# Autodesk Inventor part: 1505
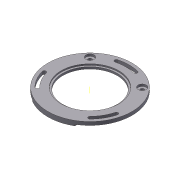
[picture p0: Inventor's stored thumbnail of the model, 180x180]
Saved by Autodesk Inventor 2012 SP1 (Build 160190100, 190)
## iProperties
Created: 2012-02
Part Number: 1505
Material: Aluminum-6061
Document SubType Name: Modeling
Designer: LACO
Density: 2.71 g/cm^3
Mass: 182.135 g
Surface Area: 295.447 cm^2
Volume: 67.2084 cm^3
Author: LACO
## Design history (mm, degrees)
sketch "Sketch1"
  geometry: C1 r 78.74 at (0, 0); A1 r 50.8 centre (0, 0) between (-41.102, 29.854) and (-41.102, -29.854); 3 further points
  constraints: 4 point on circle, 2 centre point, 2 coincident
  dimensions: "d25" = 157.48 diameter of C1; "d26" = 101.6 diameter of A1
extrude "Extrusion1" new body sketch "Sketch1" stored distance "d1" = 6.35; taper "d2" = 0 deg
sketch "Sketch5"
  geometry: C1 r 50.8 at (0, 0) reference; C2 r 78.74 at (0, 0) reference; C3 r 53.975 at (0, 0)
  constraints: 1 centre point, 1 coincident
  dimensions: "d36" = 3.175 radial gap between concentric circles of C1 C3
extrude "Extrusion3" cut sketch "Sketch5" distance "d37" = 2.54; taper "d38" = 0 deg
sketch "Sketch6"
  geometry: L1 (0, 0)-(78.74, 0); L2 (0, 0)-(76.057, -20.379); L3 (68.191, -39.37)-(0, 0); L4 (0, 0)-(55.678, -55.678); L5 (0, 0)-(-55.678, -55.678); L6 (-68.191, -39.37)-(0, 0); L7 (0, 0)-(-76.057, -20.379); L8 (0, 0)-(0, 78.74); L9 (0, 0)-(20.379, 76.057); L10 (-20.379, 76.057)-(0, 0); C1 r 66.586 at (0, 0); C2 r 53.975 at (0, 0) reference; A1 r 69.85 centre (0, 0) between (67.47, -18.079) and (49.391, -49.391); A2 r 3.264 centre (67.47, -18.079) between (64.317, -17.234) and (70.623, -18.923); A3 r 3.264 centre (49.391, -49.391) between (47.083, -47.083) and (51.699, -51.699); A4 r 3.264 centre (-49.391, -49.391) between (-47.083, -47.083) and (-51.699, -51.699); A5 r 3.264 centre (-67.47, -18.079) between (-64.317, -17.234) and (-70.623, -18.923); A6 r 66.586 centre (0, 0) between (-64.317, -17.234) and (-47.083, -47.083); A7 r 73.114 centre (0, 0) between (-70.623, -18.923) and (-51.699, -51.699); A8 r 66.586 centre (0, 0) between (47.083, -47.083) and (64.317, -17.234); A9 r 73.114 centre (0, 0) between (51.699, -51.699) and (70.623, -18.923); A10 r 3.264 centre (-18.079, 67.47) between (-18.923, 70.623) and (-17.234, 64.317); A11 r 3.264 centre (18.079, 67.47) between (18.923, 70.623) and (17.234, 64.317); A12 r 73.114 centre (0, 0) between (18.923, 70.623) and (-18.923, 70.623); A13 r 66.586 centre (0, 0) between (17.234, 64.317) and (-17.234, 64.317); 2 further points
  constraints: 30 point on circle, 20 end point, 17 point on line, 14 centre point, 6 tangent, 3 coincident, 3 concentric, 1 horizontal, 1 perpendicular, 17 other
  dimensions: "d51" = 30 deg angle of L1 L3; "d52" = 30 deg angle of L1 L6; "d53" = 15 deg angle of L6 L7; "d54" = 15 deg angle of L5 L6; "d55" = 15 deg angle of L3 L4; "d56" = 15 deg angle of L2 L3; "d57" = 3.2639 radial gap between concentric circles of A1 C1; "d58" = 3.2639 dimension on A1; "d59" = 15 deg angle of L8 L10; "d60" = 15 deg angle of L9 L8; "d64" = 139.7 diameter of A1
extrude "Extrusion4" cut sketch "Sketch6" stored distance "d49" = 2.54; taper "d50" = 0 deg
sketch "Sketch9"
  geometry: L1 (39.687, 68.007)-(39.687, 57.15); L2 (39.687, 57.15)-(-39.688, 57.15); L3 (-39.688, 57.15)-(-39.688, 68.007); L4 (0, 0)-(0, 78.74); A1 r 66.586 centre (0, 0) between (-17.234, -64.317) and (17.234, -64.317) reference; A2 r 78.74 centre (0, 0) between (0, 78.74) and (39.687, 68.007) reference
  constraints: 8 end point, 3 point on circle, 2 parallel, 1 perpendicular, 1 vertical, 1 other
  dimensions: "d81" = 57.15 distance from line of L2 A1.centre; "d82" = 79.375 distance of L1.end L2.end
extrude "Extrusion6" join sketch "Sketch9" distance "d83" = 2.54; taper "d84" = 0 deg
sketch "Sketch4"
  geometry: L1 (0, 0)-(66.04, 0); L2 (0, 0)-(0, 78.74); L3 (0, 0)-(48.942, 48.942); L4 (-48.942, 48.942)-(0, 0); A1 r 69.215 centre (0, 0) between (48.942, 48.942) and (-48.942, 48.942)
  constraints: 8 end point, 2 point on circle, 1 centre point, 1 coincident, 1 horizontal, 1 perpendicular, 1 vertical alignment, 1 other
  dimensions: "d61" = 45 deg angle of L2 L4; "d62" = 45 deg angle of L2 L3; "d63" = 9.525 dimension on A1
hole "Hole2" sketch "Sketch4" at (-48.942, 48.942), (48.942, 48.942) diameter "d29" = 6.7564; stored, may be unused: countersink angle "d33" = 82 deg, drill point angle "d35" = 118 deg; dims "d30" = 3.175, "d31" = 15.24, "d32" = 4.064, "d34" = 5.08
sketch "Sketch10"
  geometry: L1 (39.687, 68.007)-(39.687, 57.15) reference; L2 (-39.688, 57.15)-(-39.688, 68.007) reference; L3 (39.687, 57.15)-(-39.688, 57.15) reference; 2 further points
  dimensions: "d85" = 6.604 distance from line of point (-33.084, 64.262) L2; "d86" = 7.112 distance from line of L3 point (-33.084, 64.262); "d87" = 6.604 distance from line of L1 point (33.083, 64.262); "d88" = 7.112 distance from line of L3 point (33.083, 64.262)
hole "Hole4" sketch "Sketch10" at (-33.084, 64.262), (33.083, 64.262) diameter "d89" = 4.9784; stored, may be unused: countersink angle "d93" = 82 deg, drill point angle "d95" = 118 deg; dims "d90" = 6.35, "d91" = 9.525, "d92" = 6.35, "d94" = 7.112
sketch "Sketch12"
  geometry: C1 r 3.378 at (48.942, -48.942) reference; C2 r 3.378 at (-48.942, -48.942) reference; C3 r 9.525 at (-48.942, -48.942); C4 r 9.525 at (48.942, -48.942); A1 r 78.74 centre (0, 0) between (-39.688, 68.007) and (39.687, 68.007) reference
  constraints: 2 centre point, 2 coincident, 1 equal radius, 1 tangent
extrude "Extrusion7" join sketch "Sketch12" distance "d96" = 2.54; taper "d97" = 0 deg
body "Solid1"
other parameters: "d39" = 60 deg, "d40" = 60 deg, "d45" = 18 deg, "d46" = 18 deg, "d47" = 18 deg, "d48" = 18 deg
